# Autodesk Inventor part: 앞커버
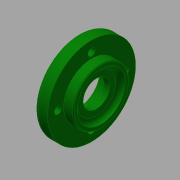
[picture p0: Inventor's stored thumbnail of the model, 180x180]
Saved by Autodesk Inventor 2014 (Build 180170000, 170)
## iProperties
Created: 2015-12
Part Number: 앞커버
Material: 일반
Document SubType Name: Modeling
Designer: mduedu
Density: 1 g/cm^3
Appearance: Dark Green
Author: mduedu
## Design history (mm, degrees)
sketch "스케치1"
  geometry: L1 (0, 0)-(14, 0); L2 (14, 0)-(14, 17.5); L3 (14, 17.5)-(8, 17.5); L4 (8, 17.5)-(8, 27.5); L5 (8, 27.5)-(0, 27.5); L6 (0, 27.5)-(0, 0)
  constraints: 12 end point, 4 parallel, 1 horizontal, 1 perpendicular
  dimensions: "d0" = 14 distance between parallel lines of L2 L6; "d2" = 8 distance of L4.end L5.end; "d3" = 55 diameter of L5 L1; "d4" = 35 diameter of L3 L1
revolve "회전1" sketch "스케치1" stored, may be unused: angle "d5" = 90 deg
hole "구멍1" diameter "d8" = 30; stored, may be unused: countersink angle "d12" = 90 deg, drill point angle "d14" = 0 deg; dims "d6" = 10, "d7" = 10, "d9" = 6, "d10" = 4, "d11" = 2, "d13" = 3
hole "구멍2" diameter "d17" = 25; stored, may be unused: countersink angle "d21" = 90 deg, drill point angle "d23" = 0 deg; dims "d15" = 10, "d16" = 10, "d18" = 6, "d19" = 4, "d20" = 2, "d22" = 7.3
hole "구멍3" diameter "d26" = 16.5; stored, may be unused: countersink angle "d30" = 90 deg, drill point angle "d32" = 0 deg; dims "d24" = 10, "d25" = 10, "d27" = 6, "d28" = 4, "d29" = 2, "d31" = 7.3
fillet "모깎기1" dims "d33" = 0.3
chamfer "모따기1" distance "d34" = 1; stored, may be unused: second distance "d35" = 2, angle "d36" = 30 deg
fillet "모깎기2" dims "d37" = 3
fillet "모깎기3" dims "d38" = 2
chamfer "모따기2" distance "d39" = 0.5; stored, may be unused: second distance "d40" = 2, angle "d41" = 45 deg
sketch "스케치2" dims "d42" = 42
  geometry: 9 further points
  constraints: 3 coincident, 2 vertical alignment, 9 other
  dimensions: "d46" = 360 deg dimension on point (0, 0) point (0, 21) (derived)
sketch "스케치3"
  geometry: 4 further points
hole "구멍4" sketch "스케치3" at (-21, 0), (0, -21), (21, 0), (0, 21) diameter "d50" = 4.5; stored, may be unused: countersink angle "d54" = 90 deg, drill point angle "d56" = 0 deg; dims "d51" = 6, "d52" = 8, "d53" = 4.6, "d55" = 8
node "솔리드1"
